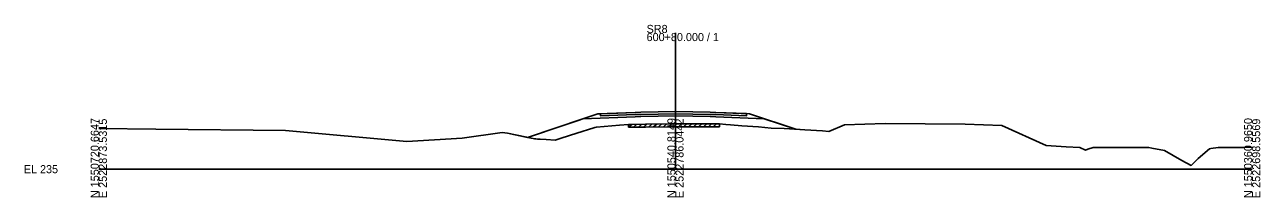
# Model space of a CAD drawing. Extents: x -26 to 2803, y -10 to 19537.
# Drawn here: x -25.7 to 402.8, y 8990.3 to 9049.9 of the extents above; entities that cross this region are included whole.
import ezdxf

# ---------------------------------------------------------------- set-up
doc = ezdxf.new("R2010")
doc.units = 0
for name, color, linetype in [('1', 7, 'Continuous'), ('Draft_XS_Grid', 7, 'Continuous'), ('Draft_XS_Text', 7, 'Continuous'), ('DTM_P_SUBGRADE_1', 7, 'Continuous'), ('DTM_X_GROUND', 7, 'Continuous'), ('SLOPE_STAKES_FILL', 7, 'Continuous'), ('XS_P_ASPHALT', 7, 'Continuous'), ('XS_P_SHOULDER', 7, 'Continuous')]:
    doc.layers.add(name, color=color, linetype=linetype)

msp = doc.modelspace()

# ---------------------------------------------------------------- linework, layer by layer
at = {"layer": '1'}
for p, q in [((200, 9000), (200, 9047.09)), ((0, 9000), (200, 9000)), ((200, 9000), (400, 9000))]:
    msp.add_line(p, q, dxfattribs=at)
at = {"layer": 'Draft_XS_Grid'}
for p, q in [((183.74, 9014.48), (184.91, 9015.5)), ((183.74, 9014.48), (183.74, 9015.48)), ((183.74, 9014.48), (189.6, 9014.56)), ((185.47, 9014.5), (186.64, 9015.52)), ((187.2, 9014.53), (188.37, 9015.54)), ((188.93, 9014.55), (190.1, 9015.57)), ((189.6, 9014.56), (197.81, 9014.67)), ((190.66, 9014.57), (191.83, 9015.59)), ((192.39, 9014.6), (193.56, 9015.61)), ((194.12, 9014.62), (195.29, 9015.64)), ((195.85, 9014.65), (197.02, 9015.66)), ((197.58, 9014.67), (198.75, 9015.68)), ((197.81, 9014.67), (198.84, 9014.69)), ((198.84, 9014.69), (199.58, 9014.7)), ((199.31, 9014.69), (200.46, 9015.69)), ((199.58, 9014.7), (200, 9014.69)), ((200, 9014.69), (205.27, 9014.68)), ((201.04, 9014.69), (202.18, 9015.69)), ((202.77, 9014.69), (203.91, 9015.68)), ((204.5, 9014.68), (205.64, 9015.68)), ((205.27, 9014.68), (209, 9014.67)), ((206.22, 9014.67), (207.37, 9015.67)), ((207.95, 9014.67), (209.1, 9015.67)), ((209, 9014.67), (211.46, 9014.66)), ((209.68, 9014.66), (210.83, 9015.66)), ((211.41, 9014.66), (212.56, 9015.66)), ((211.46, 9014.66), (215.27, 9014.65)), ((213.14, 9014.65), (214.29, 9015.65)), ((215.27, 9015.65), (215.27, 9014.65))]:
    msp.add_line(p, q, dxfattribs=at)
at = {"layer": 'Draft_XS_Text'}
for p, q in [((253.19, 9013.08), (258.62, 9015.34)), ((258.62, 9015.34), (272.75, 9015.83)), ((272.75, 9015.83), (286.6, 9015.7)), ((286.6, 9015.7), (300.46, 9015.59)), ((300.46, 9015.59), (313.17, 9015.15)), ((313.17, 9015.15), (328.58, 9008.19))]:
    msp.add_line(p, q, dxfattribs=at)
for points in [[(0, 9014.01), (19.82, 9013.88), (64.74, 9013.38), (106.88, 9009.59), (126.02, 9010.7), (139.91, 9012.73), (141.73, 9012.46), (151.22, 9010.47), (151.57, 9010.45), (152.11, 9010.42), (153.06, 9010.37), (155.18, 9010.25), (158.31, 9010.08), (160.39, 9010.76), (165.75, 9012.47), (171.7, 9014.3), (172.09, 9014.42), (172.59, 9014.57), (180.57, 9015.22), (183.74, 9015.48), (189.6, 9015.56), (197.81, 9015.67), (198.84, 9015.69), (199.58, 9015.7), (200, 9015.69), (205.27, 9015.68), (209, 9015.67), (211.46, 9015.66), (215.27, 9015.65), (217.43, 9015.48), (219.06, 9015.35), (223.08, 9015.04), (228.76, 9014.62), (233.22, 9014.23), (237.68, 9014.06), (244.91, 9013.6), (250.96, 9013.22), (253.19, 9013.08)], [(328.58, 9008.19), (335.55, 9007.76), (340.21, 9007.48), (342.21, 9006.57), (343.01, 9006.91), (344.82, 9007.5), (349.87, 9007.44), (364.15, 9007.48), (365.19, 9007.29), (369.66, 9006.49), (375.63, 9003.02), (378.86, 9001.3), (381.29, 9003.69), (385.22, 9007.06), (385.73, 9007.13), (388.27, 9007.49), (397.2, 9007.52), (400, 9007.58)]]:
    msp.add_lwpolyline(points, dxfattribs=at)
at = {"layer": 'DTM_P_SUBGRADE_1'}
for p, q in [((186, 9018.13), (167.91, 9017.41)), ((188, 9018.17), (186, 9018.13)), ((188, 9018.17), (200, 9018.41)), ((200, 9018.41), (212, 9018.17)), ((212, 9018.17), (214, 9018.13)), ((214, 9018.13), (230.79, 9017.46))]:
    msp.add_line(p, q, dxfattribs=at)
at = {"layer": 'DTM_X_GROUND'}
for p, q in [((173.04, 9019.11), (148.66, 9011.01)), ((186, 9019.63), (173.04, 9019.11)), ((188, 9019.67), (186, 9019.63)), ((188, 9019.67), (200, 9019.91)), ((200, 9019.91), (212, 9019.67)), ((212, 9019.67), (214, 9019.63)), ((214, 9019.63), (225.68, 9019.16)), ((225.68, 9019.16), (241.77, 9013.8))]:
    msp.add_line(p, q, dxfattribs=at)
at = {"layer": 'SLOPE_STAKES_FILL'}
for p, q in [((148.66, 9011.01), (173.04, 9019.11)), ((173.04, 9019.11), (186, 9019.63)), ((186, 9019.63), (188, 9019.67)), ((188, 9019.67), (200, 9019.91)), ((200, 9019.91), (212, 9019.67)), ((212, 9019.67), (214, 9019.63)), ((214, 9019.63), (225.68, 9019.16)), ((225.68, 9019.16), (241.77, 9013.8)), ((253.19, 9013.08), (258.62, 9015.34)), ((258.62, 9015.34), (272.75, 9015.83)), ((272.75, 9015.83), (286.6, 9015.7)), ((286.6, 9015.7), (300.46, 9015.59)), ((300.46, 9015.59), (313.17, 9015.15)), ((313.17, 9015.15), (328.58, 9008.19))]:
    msp.add_line(p, q, dxfattribs=at)
for points in [[(0, 9014.01), (19.82, 9013.88), (64.74, 9013.38), (106.88, 9009.59), (126.02, 9010.7), (139.91, 9012.73), (141.73, 9012.46), (148.66, 9011.01)], [(241.77, 9013.8), (244.91, 9013.6), (250.96, 9013.22), (253.19, 9013.08)], [(328.58, 9008.19), (335.55, 9007.76), (340.21, 9007.48), (342.21, 9006.57), (343.01, 9006.91), (344.82, 9007.5), (349.87, 9007.44), (364.15, 9007.48), (365.19, 9007.29), (369.66, 9006.49), (375.63, 9003.02), (378.86, 9001.3), (381.29, 9003.69), (385.22, 9007.06), (385.73, 9007.13), (388.27, 9007.49), (397.2, 9007.52), (400, 9007.58)]]:
    msp.add_lwpolyline(points, dxfattribs=at)
at = {"layer": 'XS_P_ASPHALT'}
for p, q in [((174.04, 9018.4), (174.04, 9019.15)), ((186, 9018.88), (174.04, 9018.4)), ((188, 9018.92), (186, 9018.88)), ((188, 9018.92), (200, 9019.16)), ((200, 9019.16), (212, 9018.92)), ((212, 9018.92), (214, 9018.88)), ((214, 9018.88), (224.65, 9018.46)), ((224.65, 9018.46), (224.65, 9019.21))]:
    msp.add_line(p, q, dxfattribs=at)
at = {"layer": 'XS_P_SHOULDER'}
for points in [[(165.75, 9012.47), (171.7, 9014.3), (172.09, 9014.42), (172.59, 9014.57), (180.57, 9015.22), (183.74, 9015.48), (189.6, 9015.56), (197.81, 9015.67), (198.84, 9015.69), (199.58, 9015.7), (200, 9015.69), (205.27, 9015.68), (209, 9015.67), (211.46, 9015.66), (215.27, 9015.65), (217.43, 9015.48), (219.06, 9015.35), (223.08, 9015.04), (228.76, 9014.62), (233.22, 9014.23), (237.68, 9014.06), (241.77, 9013.8), (230.79, 9017.46), (214, 9018.13), (212, 9018.17), (200, 9018.41), (188, 9018.17), (186, 9018.13), (167.91, 9017.41), (148.66, 9011.01), (151.22, 9010.47), (151.57, 9010.45), (152.11, 9010.42), (153.06, 9010.37), (155.18, 9010.25), (158.31, 9010.08), (160.39, 9010.76)], [(212, 9018.17), (214, 9018.13), (230.79, 9017.46), (225.68, 9019.16), (224.65, 9019.21), (224.65, 9018.46), (214, 9018.88), (212, 9018.92), (200, 9019.16), (188, 9018.92), (186, 9018.88), (174.04, 9018.4), (174.04, 9019.15), (173.04, 9019.11), (167.91, 9017.41), (186, 9018.13), (188, 9018.17), (200, 9018.41)], [(200, 9019.91), (212, 9019.67), (214, 9019.63), (224.65, 9019.21), (224.65, 9018.46), (214, 9018.88), (212, 9018.92), (200, 9019.16), (188, 9018.92), (186, 9018.88), (174.04, 9018.4), (174.04, 9019.15), (186, 9019.63), (188, 9019.67)]]:
    msp.add_lwpolyline(points, close=True, dxfattribs=at)

# ---------------------------------------------------------------- texts
at = {"layer": '1'}
for s, p in [('SR8', (190, 9047.09)), ('600+80.000 / 1', (190, 9044.29)), ('EL 235', (-26, 8998.6))]:
    msp.add_text(s, height=2.8, dxfattribs=at).set_placement(p)
for s, p in [('N 1550720.6647', (0, 8990)), ('E 2522873.5315', (2.8, 8990)), ('N 1550540.8149', (200, 8990)), ('E 2522786.0442', (202.8, 8990)), ('N 1550360.9650', (400, 8990)), ('E 2522698.5569', (402.8, 8990))]:
    msp.add_text(s, height=2.8, rotation=90, dxfattribs=at).set_placement(p)

doc.saveas('drawing.dxf')
